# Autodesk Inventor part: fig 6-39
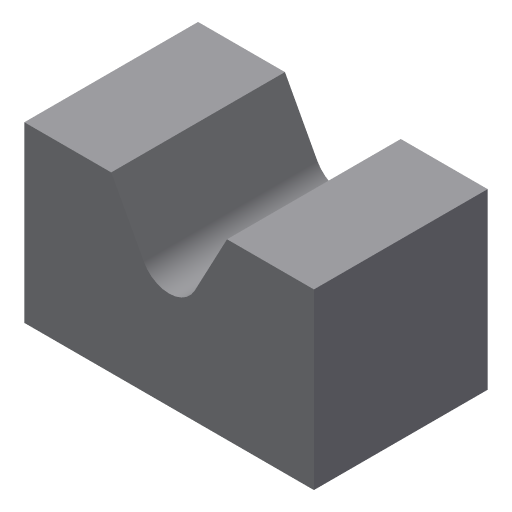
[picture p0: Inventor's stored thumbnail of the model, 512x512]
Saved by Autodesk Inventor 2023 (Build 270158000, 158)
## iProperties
Created: 2005-12
Part Number: fig 6-39
Document SubType Name: Modeling
Designer: CADCIM
Density: 1 g/cm^3
Material: Generic
Appearance: Default
Author: CADCIM
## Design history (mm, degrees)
sketch "Sketch1"
  geometry: L1 (10, 15)-(25, 15); L2 (25, 15)-(25, -15); L3 (25, -15)-(-25, -15); L4 (-25, -15)-(-25, 15); L5 (-25, 15)-(-10, 15); L6 (-10, 15)-(-2, 0); L7 (-2, 0)-(2, 0); L8 (2, 0)-(10, 15); 1 further point
  constraints: 16 end point, 3 equal length, 3 parallel, 1 collinear, 1 horizontal, 1 perpendicular, 1 other
  dimensions: "d0" = 50 distance of L2.end L3.end; "d1" = 25 distance from line of point (0, 0) L2; "d2" = 30 distance of L1.end L2.end; "d3" = 15 distance of L1.start L1.end; "d4" = 15 distance between parallel lines of L1 L7; "d5" = 4 distance of L6.end L7.end; "d6" = 15 distance from line of point (0, 0) L3
extrude "Extrusion1" new body sketch "Sketch1" stored distance "d7" = 30; taper "d8" = 0 deg
fillet "Fillet4" dims "d11" = 5
body "Solid1"
